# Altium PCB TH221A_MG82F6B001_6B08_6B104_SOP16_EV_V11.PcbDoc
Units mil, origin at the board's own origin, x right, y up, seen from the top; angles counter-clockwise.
Board outline 2244.09 x 2637.8 mil, 2 copper layers (Top Layer, Bottom Layer); 94 components, 67 nets, 312 pads, 160 vias.
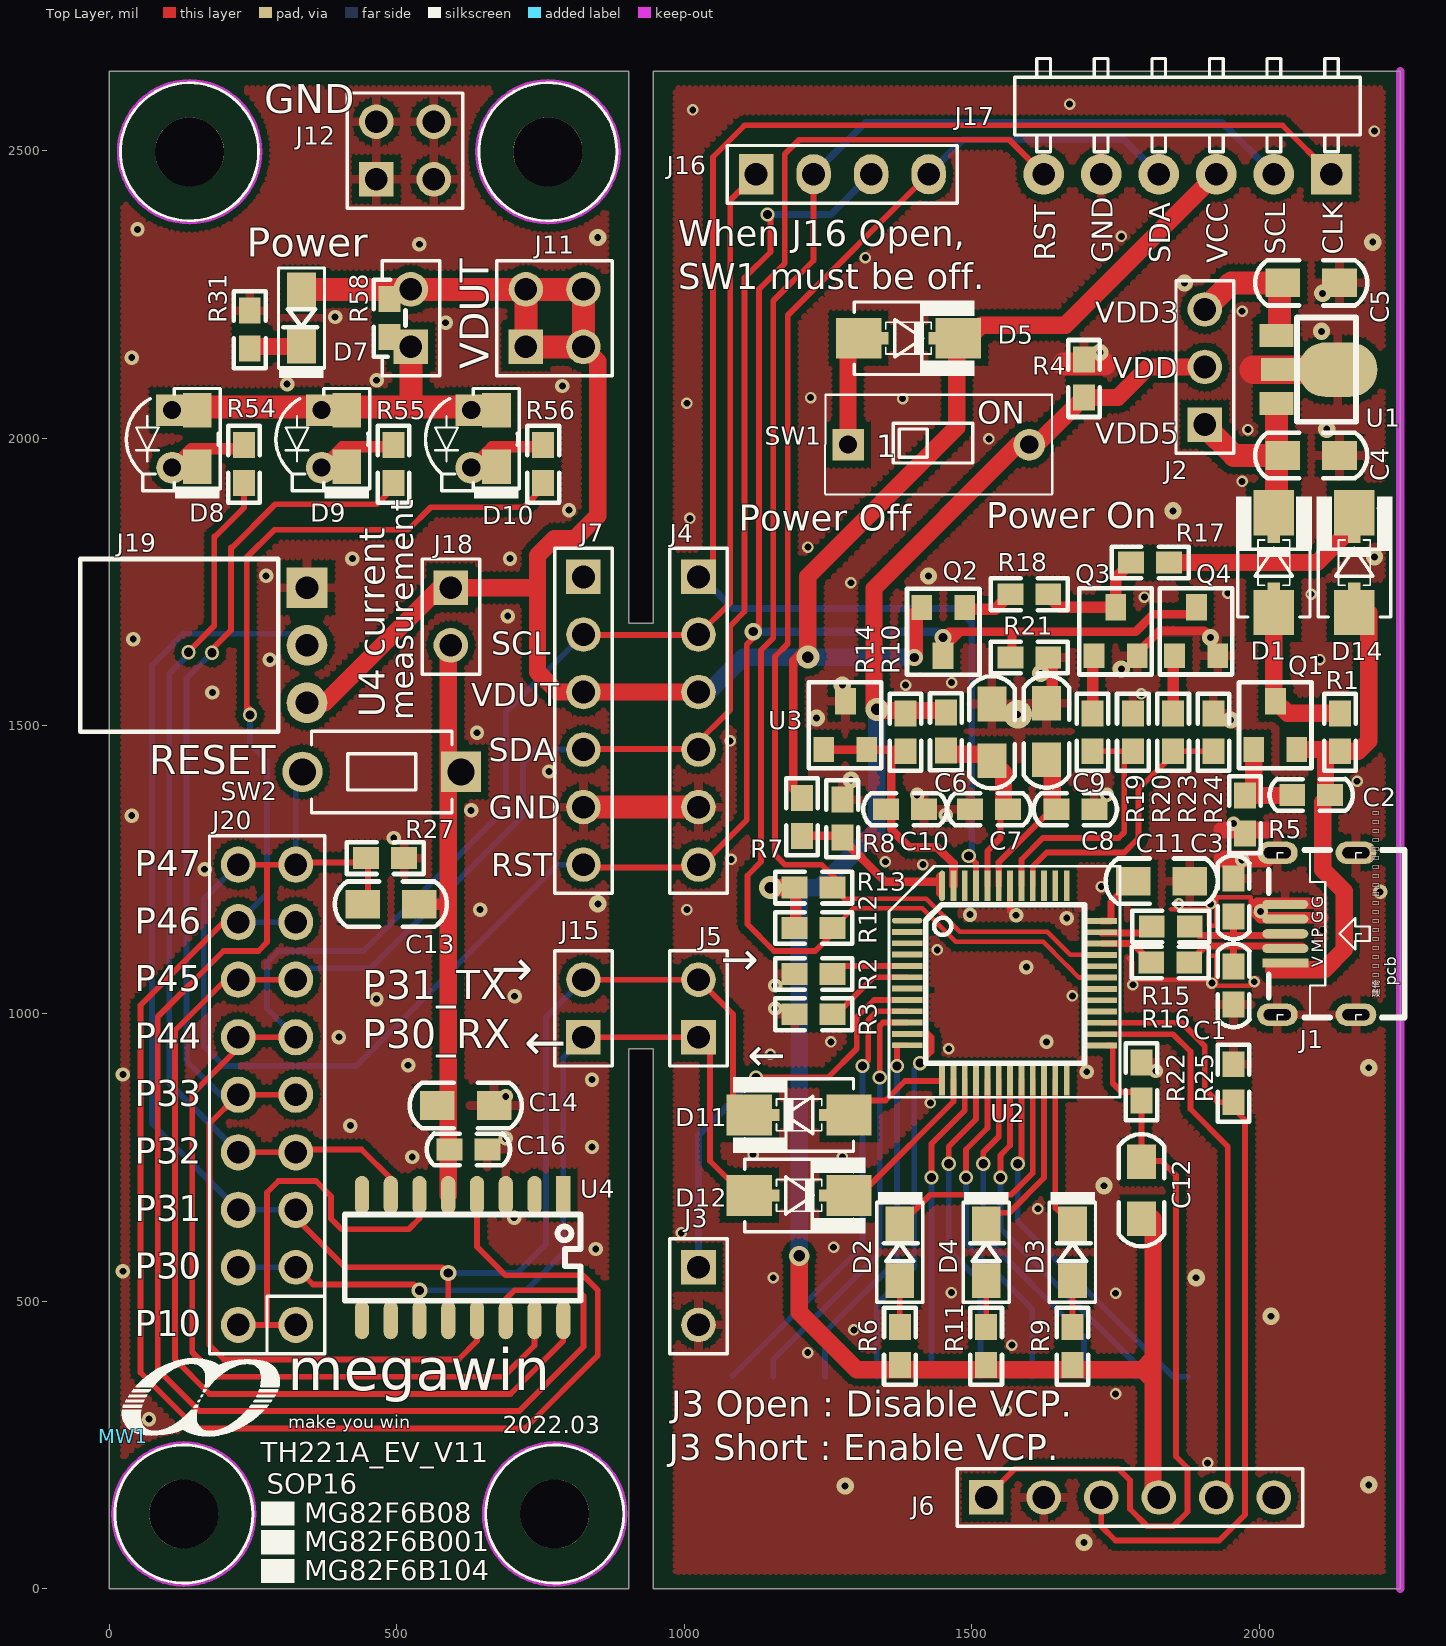
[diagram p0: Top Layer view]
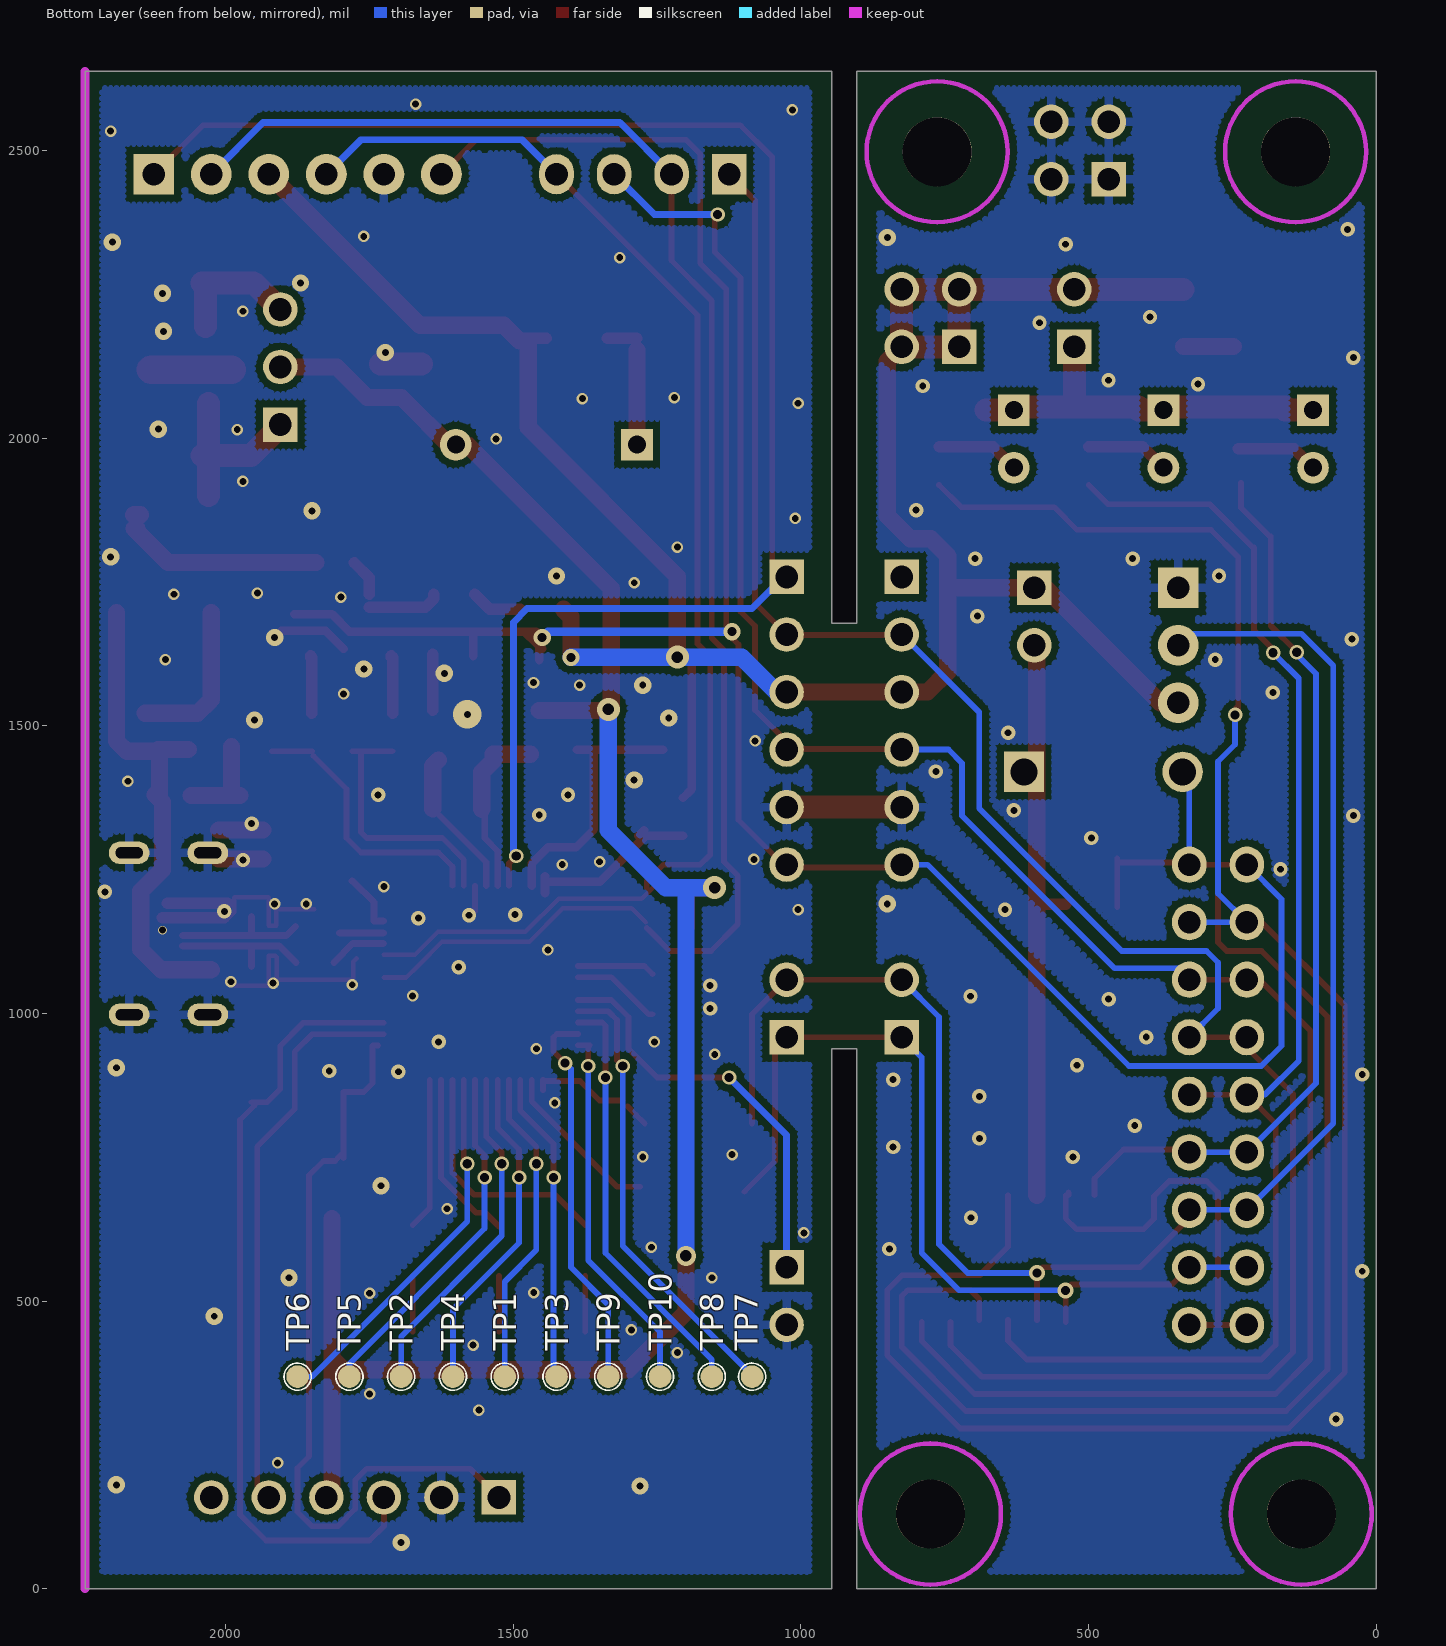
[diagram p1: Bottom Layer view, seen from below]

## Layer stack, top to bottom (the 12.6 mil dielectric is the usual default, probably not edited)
Top Layer: signal copper 1.4
Dielectric: dielectric 12.6, FR-4, Dk 4.8
Bottom Layer: signal copper 1.4

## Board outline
0,0 0,2637.8 902.99,2637.8 902.99,1678.74 946.3,1678.74 946.3,2637.8 2244.09,2637.8 2244.09,0 946.3,0 946.3,938.74 902.99,938.74 902.99,0

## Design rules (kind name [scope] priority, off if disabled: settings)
Clearance 12 [All] p1 off: gap=12
Clearance 7 [All] p2 off: gap=7
Clearance 6 [All] p3: gap=6
HoleSize 500-HoleSize [All] p1: absolutevalues=TRUE maxlimit=1500 minlimit=1 maxpercent=80.000 minpercent=20.000
PolygonConnect VIA [ISVIA] p1: connectstyle=Direct reliefconductorwidth=10 reliefentries=4 polygonreliefangle="90 Angle"
PolygonConnect "15 PolygonConnect" [All] p2: connectstyle=Relief reliefconductorwidth=15 reliefentries=4 polygonreliefangle="90 Angle"
RoomDefinition 2_MG82F6B001_6B08_6B104_V11 [InComponentClass('2_MG82F6B001_6B08_6B104_V11')] p1: confinementstyle=ConfineIn formatcopy=TRUE lockcomponents=FALSE outline -320,-225 2540,-225 2540,2735 -320,2735
RoomDefinition 1_MLink_V11 [InComponentClass('1_MLink_V11')] p2: confinementstyle=ConfineIn formatcopy=TRUE lockcomponents=FALSE outline -485,-135 2605,-135 2605,2695 -485,2695
RoutingVias [All] p1: holewidth=16 width=28 viastyle="Through Hole" minholewidth=16 minwidth=25 maxholewidth=28 maxwidth=50
ShortCircuit [All] p1 off: allowed=FALSE
SilkscreenOverComponentPads [All] p1: minsilkscreentomaskgap=10
SolderMaskExpansion [All] p1: expansion=4
UnRoutedNet [All] p1 off:
Width [All] p1: maxlimit=100 minlimit=6 preferedwidth=10
24 further rules are at their usual default settings.

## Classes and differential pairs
component class 1_MLink_V11: C1 C2 C3 C4 C5 C6 C7 C8 C9 C10 C11 C12 D1 D2 D3 D4 D5 D11 D12 D14 J1 J2 J3 J4 J5 J6 J16 J17 MW1 Q1 Q2 Q3 Q4 R1 R2 R3 R4 R5 R6 R7 R8 R9 R10 R11 R12 R13 R14 R15 R16 R17 R18 R19 R20 R21 R22 R23 R24 R25 SW1 TP1 TP2 TP3 TP4 TP5 TP6 TP7 TP8 TP9 TP10 U1 U2 U3
component class 2_MG82F6B001_6B08_6B104_V11: C13 C14 C16 D7 D8 D9 D10 J7 J11 J12 J15 J18 J19 J20 R27 R31 R54 R55 R56 R58 SW2 U4

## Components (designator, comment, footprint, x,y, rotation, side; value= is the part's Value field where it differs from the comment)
C1 "15pF" 0603C#1 1954.65,1048.74 r90 top
C2 "0.1uF" 0603C#1 2089.61,1380 r0 top
C3 "15pF" 0603C#1 1954.65,1201.74 r270 top
C4 "4.7uF" 0805C 2089.61,1970 r0 top
C5 "4.7uF" 0805C 2089.61,2270 r0 top
C6 "4.7uF" 0805C 1534.61,1488.74 r90 top
C7 "0.1uF" 0603C#1 1529.65,1355 r180 top
C8 "0.1uF" 0603C#1 1679.65,1355 r0 top
C9 "4.7uF" 0805C 1629.61,1490 r90 top
C10 "0.1uF" 0603C#1 1383.7,1355 r180 top
C11 "4.7uF" 0805C 1829.61,1230 r0 top
C12 "4.7uF" 0805C 1794.65,692.74 r90 top
C13 "4.7uF" 0805C 490,1190 r0 top
C14 "4.7uF" 0805C 620,840 r0 top
C16 "0.1uF" 0603C#2 624.65,763.74 r0 top
D1 "1N5817" DIODE_SMA_SOD323 2024.61,1783.74 r90 top
D2 "Yellow" 0805D 1374.65,585 r90 top
D3 "Green" 0805D 1674.65,585 r90 top
D4 "Red" 0805D 1524.65,585 r90 top
D5 "1N5817" DIODE_SMA_SOD323 1389.61,2173.74 r0 top
D7 "Yellow" 0805D 334.65,2208.74 r270 top
D8 "Red" LED38+0805 109.65,1998.74 r270 top
D9 "Yellow" LED38+0805 369.65,1998.74 r270 top
D10 "Green" LED38+0805 629.65,1998.74 r270 top
D11 "1N5817" DIODE_SMA_SOD323 1199.65,823.74 r180 top
D12 "1N5817" DIODE_SMA_SOD323 1199.65,683.74 r0 top
D14 "1N5817" DIODE_SMA_SOD323 2164.61,1783.74 r90 top
J1 "MICRO_USB" USB_MICRO_7.X6P065 2167.41,1138.59 r90 top
J2 "2&3 (0 ohm)" PS3P254 1904.65,2023.74 r90 top
J3 "VCP Option" PS2P254 1024.65,558.74 r270 top locked
J4 "OnBoard ICP/SWD Connector" PS6P254 1024.65,1758.74 r270 top locked
J5 "NC" PS2P254 1024.65,958.74 r90 top locked
J6 "CON6" PS6P254 1524.65,158.74 r0 top locked
J7 "CON6" PS6P254 824.65,1758.74 r270 top locked
J11 "CONN SOCKET 2x2/SM" PS2X2P254 724.65,2158.74 r0 top
J12 "CONN SOCKET 2x2/SM" PS2X2P254 464.65,2450 r0 top
J15 "NC" PS2P254 824.65,958.74 r90 top
J16 "When J16 Open, SW1 must be off." PS4P254 1124.65,2458.74 r0 top locked
J17 "Off Board ICP/SWD Connector" PS6P254_90 2124.65,2458.74 r180 top locked
J18 "JUMPER" PS2P254 594.09,1740 r270 top
J19 "3P2.54_F_90" PS3P254f_90 344.09,1740 r270 top
J20 "CON18A" PS9X2P254 324.65,458.74 r90 top
MW1 "MW-A4" MEGAWIN_3.4 24.65,265 r0 top
Q1 "IRLML6402" SOT23 2027.15,1500.71 r0 top
Q2 "2N3906" SOT23 1450.11,1663.74 r180 top
Q3 "3904" SOT23_132 1749.65,1663.74 r0 top
Q4 "3904" SOT23_132 1889.65,1663.74 r0 top
R1 "NC" 0603R#1 2139.65,1488.74 r270 top
R2 "0" 0603R#1 1224.65,1068.74 r0 top
R3 "NC" 0603R#1 1224.65,998.74 r0 top
R4 "3.3K" 0603R#1 1694.65,2103.74 r270 top
R5 "1M" 0603R#1 1974.65,1345.74 r270 top
R6 "1K" 0603R#1 1374.65,422 r270 top
R7 "30K" 0603R#1 1204.65,1341.74 r90 top
R8 "10K" 0603R#1 1274.65,1338.74 r270 top
R9 "1K" 0603R#1 1674.65,422 r270 top
R10 "10" 0603R#1 1454.61,1490 r90 top
R11 "1K" 0603R#1 1524.65,422 r270 top
R12 "1.5K" 0603R#1 1224.65,1148.74 r180 top
R13 "1.5K" 0603R#1 1224.65,1218.74 r180 top
R14 "1K" 0603R#1 1384.61,1488.74 r270 top
R15 "30" 0603R#1 1845.48,1151.05 r180 top
R16 "30" 0603R#1 1844.65,1088.74 r180 top
R17 "4.7K" 0603R#1 1809.61,1783.74 r0 top
R18 "1K" 0603R#1 1599.65,1728.74 r0 top
R19 "4.7K" 0603R#1 1709.65,1488.74 r270 top
R20 "10K" 0603R#1 1779.65,1488.74 r270 top
R21 "1M" 0603R#1 1599.65,1618.74 r180 top
R22 "47K" 0603R#1 1794.65,881.74 r90 top
R23 "4.7K" 0603R#1 1849.65,1488.74 r270 top
R24 "10K" 0603R#1 1919.65,1488.74 r270 top
R25 "47K" 0603R#1 1954.65,878.74 r270 top
R27 "47K" 0603R#2 480,1270 r0 top
R31 "1K" 0603R#1 244.65,2188.74 r90 top
R54 "470" 0603R#1 234.65,1955 r270 top
R55 "470" 0603R#1 494.65,1955 r270 top
R56 "470" 0603R#1 754.65,1955 r270 top
R58 "0" PS2p254+0603 524.65,2158.74 r90 top
SW1 "SW KEY-SPST" DIP2_SW 1284.68,1988.74 r0 top
SW2 "SW TACT-SPST" SW_T_2P 474.09,1420 r180 top
TP1 "T POINT A" PIN1_1H0 1514.65,368.74 r90 bottom
TP2 "T POINT A" PIN1_1H0 1694.65,368.74 r90 bottom
TP3 "T POINT A" PIN1_1H0 1424.65,368.74 r180 bottom
TP4 "T POINT A" PIN1_1H0 1604.65,368.74 r180 bottom
TP5 "T POINT A" PIN1_1H0 1784.65,368.74 r180 bottom
TP6 "T POINT A" PIN1_1H0 1874.65,368.74 r180 bottom
TP7 "T POINT A" PIN1_1H0 1084.65,368.74 r180 bottom
TP8 "T POINT A" PIN1_1H0 1154.65,368.74 r180 bottom
TP9 "T POINT A" PIN1_1H0 1334.65,368.74 r180 bottom
TP10 "T POINT A" PIN1_1H0 1244.65,368.74 r90 bottom
U1 "AIC1734-33(SOT-89)" SOT89 2029.61,2119.06 r270 top
U2 "MG84FG516_LQFP48" LQFP48_7X7_050 1556.12,1053.13 r270 top
U3 "TL431A" SOT23 1279.61,1500.71 r0 top
U4 "MG82F6B001/08/104 SOP-16" SO16_150P127 614.65,575.74 r270 top

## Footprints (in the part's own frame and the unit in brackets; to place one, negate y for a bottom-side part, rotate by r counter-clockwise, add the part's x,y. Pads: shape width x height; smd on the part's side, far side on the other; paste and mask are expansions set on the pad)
0603C#1 [mil]
  rect 45x38 smd: 1(33,0) 2(-33,0)
  silkscreen extent -72,-28 72,28
0603C#2 [mil]
  rect 45x38 smd: 1(-33,0) 2(33,0)
  silkscreen extent -72,-28 72,28
0603R#1 [mil]
  rect 45x38 smd: 1(33,0) 2(-33,0)
  silkscreen extent -67,-28 67,28
0603R#2 [mil]
  rect 45x38 smd: 1(-33,0) 2(33,0)
  silkscreen extent -67,-28 67,28
0805C [mil]
  rect 60x50 smd: 1(-49.21,0) 2(49.21,0)
  silkscreen extent -97,-39 97,39
0805D [mil]
  rect 60x50 smd: 1(-49.21,0) 2(49.21,0)
  silkscreen extent -87,-40 104,40
DIODE_SMA_SOD323 [mm]
  rect 2x1.8 smd: 1(-2.2,0) 2(2.2,0)
  rect 0.95x0.54 smd: 1(-1.35,0) 2(1.35,0)
  silkscreen extent -2.4,-1.68 2.92,1.68
DIP2_SW [mm]
  rect 1.4x1.4 hole 0.8: 1(0,0)
  round 1.4 hole 0.8: 2(8,0)
  silkscreen extent -1.02,-2.2 9.02,2.2
LED38+0805 [mm]
  rect 1.4x1.4 hole 0.8: 1(-1.27,0)
  rect 1.524x1.27 smd: 1(-1.267,1.11) 2(1.233,1.11)
  round 1.4 hole 0.8: 2(1.27,0)
  silkscreen extent -2.23,-2.02 2.64,2.13
LQFP48_7X7_050 [mm]
  oval 0.254x1.35 smd: 1(-2.75,-4.292)
  rect 0.254x1.35 smd: 2(-2.25,-4.292) 3(-1.75,-4.292) 4(-1.25,-4.292) 5(-0.75,-4.292) 6(-0.25,-4.292) 7(0.25,-4.292) 8(0.75,-4.292) 9(1.25,-4.292) 10(1.75,-4.292) 11(2.25,-4.292) 12(2.75,-4.292) 25(2.763,4.292) 26(2.263,4.292) 27(1.763,4.292) 28(1.263,4.292) 29(0.763,4.292) 30(0.263,4.292) 31(-0.237,4.292) 32(-0.737,4.292) 33(-1.237,4.292) 34(-1.737,4.292) 35(-2.237,4.292) 36(-2.737,4.292)
  rect 1.35x0.254 smd: 13(4.286,-2.744) 14(4.286,-2.244) 15(4.286,-1.744) 16(4.286,-1.244) 17(4.286,-0.744) 18(4.286,-0.244) 19(4.286,0.256) 20(4.286,0.756) 21(4.286,1.256) 22(4.286,1.756) 23(4.286,2.256) 24(4.286,2.756) 37(-4.286,2.756) 38(-4.286,2.256) 39(-4.286,1.756) 40(-4.286,1.256) 41(-4.286,0.756) 42(-4.286,0.256) 43(-4.286,-0.244) 44(-4.286,-0.744) 45(-4.286,-1.244) 46(-4.286,-1.744) 47(-4.286,-2.244)
  oval 1.35x0.254 smd: 48(-4.286,-2.744)
  silkscreen extent -5.15,-5.09 5.05,5.11
MEGAWIN_3.4 [mil]
  silkscreen extent -2,0 272,135
PIN1_1H0 [mm]
  round 1 smd: 1(0,0)
  silkscreen extent -0.6,-0.6 0.6,0.6
PS2P254 [mil]
  rect 60x60 hole 39.37: 1(0,0)
  round 60 hole 39.37: 2(100,0)
  silkscreen extent -50,-50 150,50
PS2p254+0603 [mil]
  rect 60x60 hole 39.37: 1(0,0)
  rect 45x38 smd: 1(17,36.85) 2(83,36.85)
  round 60 hole 39.37: 2(100,0)
  silkscreen extent -50,-50 150,64
PS2X2P254 [mil]
  rect 60x60 hole 39.37: 1(0,0)
  round 60 hole 39.37: 2(0,100) 3(100,0) 4(100,100)
  silkscreen extent -50,-50 150,150
PS3P254 [mil]
  rect 60x60 hole 39.37: 1(0,0)
  round 60 hole 39.37: 2(100,0) 3(200,0)
  silkscreen extent -50,-50 250,50
PS3P254f_90 [mm]
  rect 1.8x1.8 hole 1: 1(0,0)
  round 1.8 hole 1: 2(2.54,0) 3(5.08,0)
  silkscreen extent -1.27,-10 6.35,-1.27
PS4P254 [mil]
  rect 60x70 hole 39.37: 1(0,0)
  oval 60x70 hole 39.37: 2(100,0) 3(200,0) 4(300,0)
  silkscreen extent -50,-50 350,50
PS6P254 [mil]
  rect 60x60 hole 39.37: 1(0,0)
  round 60 hole 39.37: 2(100,0) 3(200,0) 4(300,0) 5(400,0) 6(500,0)
  silkscreen extent -50,-50 550,50
PS6P254_90 [mm]
  rect 1.8x1.8 hole 1: 1(0,0)
  round 1.8 hole 1: 2(2.54,0) 3(5.08,0) 4(7.62,0) 5(10.16,0) 6(12.7,0)
  silkscreen extent -1.27,-5.11 13.97,-1
PS9X2P254 [mm]
  oval 1.6x1.524 hole 1: 1(0,0) 2(0,2.54) 4(2.54,2.54) 5(5.08,0) 6(5.08,2.54) 7(7.62,0) 8(7.62,2.54) 9(10.16,0) 10(10.16,2.54) 11(12.7,0) 12(12.7,2.54) 13(15.24,0) 14(15.24,2.54) 15(17.78,0) 16(17.78,2.54) 17(20.32,0) 18(20.32,2.54)
  round 1.524 hole 1: 3(2.54,0)
  silkscreen extent -1.27,-1.27 21.59,3.81
SO16_150P127 [mil]
  rect 67x25 smd: 1(-108.5,175)
  oval 67x25 smd: 2(-108.5,125) 3(-108.5,75) 4(-108.5,25) 5(-108.5,-25) 6(-108.5,-75) 7(-108.5,-125) 8(-108.5,-175) 9(108.5,-175) 10(108.5,-125) 11(108.5,-75) 12(108.5,-25) 13(108.5,25) 14(108.5,75) 15(108.5,125) 16(108.5,175)
  silkscreen extent -75,-205 75,205
SOT23 [mil]
  rect 36x43.31 smd: 1(-37.5,-41.97) 2(37.5,-41.97)
  rect 36x46.06 smd: 3(0.5,41.97)
  silkscreen extent -63,-74 63,75
SOT23_132 [mil]
  rect 36x43.31 smd: 1(-37.5,-41.97) 3(37.5,-41.97)
  rect 36x46.06 smd: 2(0.5,41.97)
  silkscreen extent -63,-74 63,75
SOT89 [mm]
  rect 1.016x1.5 smd: 1(-1.5,0) 3(1.5,0)
  oval 2.4x3.5 smd: 2(0,2.7)
  rect 1.016x2.6 smd: 2(0,0.6)
  silkscreen extent -2.3,0.9 2.3,3.5
SW_T_2P [mil]
  rect 70x70 hole 47.24: 1(-137.79,0)
  round 70 hole 47.24: 2(137.79,0)
  silkscreen extent -122,-71 122,71
USB_MICRO_7.X6P065 [mm] "J?"
  rect 0.4x2.032 smd: 1(-1.3,3.119)
  oval 0.4x2.032 smd: 2(-0.65,3.119) 3(0,3.119) 4(0.65,3.119) 5(1.3,3.119)
  oval 1x1.8 hole 0.5 slot 1.2 at 90 deg: 6(3.575,3.47) 7(3.575,0) 8(-3.575,0) 9(-3.575,3.47)
  silkscreen extent -3.83,-2.15 3.7,3.85

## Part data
C1 C3 C7 C12 C13 C14 C16: library part "CAP NP_Dup1"
C2 C8 C10: library part "CAP NP"
C4 C5: library part "C NP"
C6 C9 C11: library part CAP
D1 D5 D11 D12 D14: library part "DIODE SCHOTTKY"
D2 D3 D4: library part Led0_0
D7 D8 D9 D10: library part LED
J1: library part USB_Micro
J2 J19: library part CON3
J3 J5 J15: library part CON2
J4 J17: library part CON6
J7: library part CON6_Dup1
J16: library part CON4
MW1: library part MW_A4_2
Q1: library part "MOSFET P GSD"
Q2: library part 2N3906_0
Q3 Q4: library part "NPN BCE"
R1 R2 R3 R4: library part R_Dup4
R5 R6 R7 R8 R9 R11 R12 R13 R17 R18 R19 R22 R23 R25 R27: library part R_Dup2
R10 R14 R15 R16: library part R_Dup5
R20 R21 R24: library part R_Dup1
R31 R54 R55 R56 R58: library part R_Dup3
U1: library part AIC1722-33
U3: library part TL431/CYL
U4: library part MG82F6B001/08/104_SOP-16

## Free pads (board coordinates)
  round 120 hole 120 unplated: 0(130,130) 0(140,2497.8) 0(762.99,2497.8) 0(774.65,130)

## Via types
v1: diameter 20, hole 12, Top Layer to Bottom Layer, tented both sides, 54 vias
v2: diameter 25, hole 12, Top Layer to Bottom Layer, tented both sides, 54 vias
v3: diameter 30, hole 12, Top Layer to Bottom Layer, tented both sides, 25 vias
v4: diameter 25, hole 16, Top Layer to Bottom Layer, tented both sides, 16 vias
v5: diameter 40, hole 20, Top Layer to Bottom Layer, tented both sides, 3 vias
v6: diameter 30, hole 16, Top Layer to Bottom Layer, tented both sides, 3 vias
v7: diameter 28, hole 16, Top Layer to Bottom Layer, tented both sides, 2 vias
v8: diameter 15, hole 12, Top Layer to Bottom Layer, tented both sides, 1 vias
v9: diameter 50, hole 12, Top Layer to Bottom Layer, tented both sides, 1 vias
v10: diameter 35, hole 20, Top Layer to Bottom Layer, tented both sides, 1 vias

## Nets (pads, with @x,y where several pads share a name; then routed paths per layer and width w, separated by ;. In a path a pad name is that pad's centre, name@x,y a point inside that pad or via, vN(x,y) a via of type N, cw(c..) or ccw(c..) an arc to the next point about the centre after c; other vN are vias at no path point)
2.495V: C10.1 R14.1 U2.47 U3.1 U3.2 | length 455.3
  Top Layer w15: U3.1@1239.61,1458.74 U3.1 U3.2 1359.61,1458.74 1359.61,1455.74 1359.61,1355 1359.61,1320 1390.87,1288.74 1439.65,1288.74 1467.78,1260.6 U2.47 ; 1364.61,1458.74 1384.61,1458.74 R14.1@1389.61,1458.74
516P24: TP7.1 U2.9 | length 790.4
  Top Layer w10: v4(1309.65,908.74) 1319.65,918.74 1319.65,988.74 1334.82,1003.92 U2.9
  Bottom Layer w10: TP7.1@1083.51,369.88 1309.65,596.02 v4(1309.65,908.74)
516P25: TP8.1 U2.10 | length 736.4
  Top Layer w10: v4(1339.65,888.74) 1339.65,978.74 1345.14,984.23 U2.10
  Bottom Layer w10: TP8.1 1154.65,398.59 1339.65,583.59 v4(1339.65,888.74)
516P26: TP9.1 U2.11 | length 674.3
  Top Layer w10: U2.11 1423.84,964.55 1429.65,958.74 1429.65,933.74 v4(1409.65,913.74)
  Bottom Layer w10: TP9.1 1334.65,493.74 1399.65,558.74 1399.65,903.74 v4(1409.65,913.74)
516P27: TP10.1 U2.12 | length 649.5
  Top Layer w10: v4(1369.65,908.74) 1369.65,941.97 1366.75,944.86 U2.12
  Bottom Layer w10: TP10.1 1244.65,446.17 1369.65,571.17 v4(1369.65,908.74)
516P32: TP3.1 U2.15 | length 762.5
  Top Layer w10: v4@1429.65,713.74 v4(1429.65,715) 1429.65,773.74 1487.47,831.56 U2.15
  Bottom Layer w10: TP3.1@1429.65,373.74 1429.65,628.74 ; 1429.65,400.87 1429.65,628.74 ; v4@1429.65,713.74 1429.65,628.74
516P33: TP1.1 U2.16 | length 558.1
  Top Layer w10: v4(1459.65,738.74) 1459.65,768.74 1507.15,816.25 U2.16
  Bottom Layer w10: v4(1459.65,738.74) 1459.65,588.89 1514.65,533.89 TP1.1
516P34: TP4.1 U2.17 | length 578.7
  Top Layer w10: v4@1489.65,713.74 v4(1489.65,715) 1489.65,763.74 1526.84,800.93 U2.17
  Bottom Layer w10: v4@1489.65,713.74 1489.65,601.31 1604.65,486.31 TP4.1
516P35: TP2.1 U2.18 | length 599.3
  Top Layer w10: v4(1519.65,738.74) 1519.65,758.74 1546.52,785.62 U2.18
  Bottom Layer w10: v4(1519.65,738.74) 1519.65,613.74 1694.65,438.74 TP2.1
516P36: TP5.1 U2.19 | length 619.9
  Top Layer w10: v4@1549.65,713.74 v4(1549.65,715) 1549.65,753.74 1566.21,770.3 U2.19
  Bottom Layer w10: v4@1549.65,713.74 1549.65,626.17 1784.65,391.17 TP5.1
516P37: TP6.1 U2.20 | length 655.2
  Top Layer w10: v4(1579.65,738.74) 1585.89,744.99 U2.20
  Bottom Layer w10: v4(1579.65,738.74) 1579.65,638.59 1849.5,368.74 TP6.1
CHIP_VDD: C13.2 C14.1 C16.1 J18.2 SW2.1 U4.5 | length 1016.2
  Top Layer w20: C13.2 589.65,1190
  Top Layer w30: U4.5 589.65,763.74 589.65,840 589.65,1190 589.65,1420 589.65,1640 J18.2@589.65,1650
D+: C3.1 J1.3 R15.2 | length 231.2
  Top Layer w12: R15.2 1894.32,1135.21 2044.61,1135.21 J1.3@2074.65,1135.21 ; 1954.65,1140.21 C3.1
D-: C1.1 J1.2 R16.2 | length 239.3
  Top Layer w12: R16.2 1906.12,1117.21 2044.61,1117.21 J1.2@2074.65,1117.21 ; C1.1 1954.65,1112.21
DET_VDUT: R7.2 R8.1 U2.48 | length 318.6
  Top Layer w15: R7.2 1274.65,1308.74 R8.1@1282.2,1308.74 ; R8.1@1272.2,1318.74 R8.1@1279.93,1311.02 ; R8.1@1272.41,1305.98 1273.65,1304.74 1349.65,1228.74 1440.58,1228.74 ; U2.48@1444.65,1208.74 1444.65,1221.87 U2.48@1444.65,1238.74
DUT_CLK: J4.1 J17.1 U2.45 | length 2846.4
  Top Layer w10: J4.1 1049.65,1783.74 1049.65,2488.74 1104.65,2543.74 2039.65,2543.74 J17.1 ; v4(1494.53,1273.74) 1507.15,1261.11 U2.45
  Bottom Layer w12: J4.1 1029.65,1758.74 1084.65,1703.74 1475.87,1703.74 1499.61,1680 1499.61,1278.82 v4(1494.53,1273.74)
DUT_RST: C13.1 J4.6 J7.6 J17.6 J20.17 J20.18 Q2.3 Q4.2 R21.1 R27.1 SW2.2 U4.14 | length 6694.6
  Top Layer w10: J20.18 274.65,1258.74 ; J20.17@321.65,1261.74 318.65,1258.74 274.65,1258.74 ; J20.17@327.09,1262.44 R27.1@447,1262.44 ; C13.1@450,1185 450,1190 R27.1@450,1270 ; U4.14 689.65,503.74 704.65,518.74 814.65,518.74 824.65,508.74 ; 824.65,443.74 824.65,508.74 ; J7.6@824.65,1253.74 J4.6@1024.65,1253.74 ; J4.6@1027.65,1255.74 1108.4,1336.49 1108.4,1641.49 1125.15,1658.24 1129.65,1662.74 1129.65,1663.74 1129.65,2258.74 1174.65,2303.74 1174.65,2493.74 1199.65,2518.74 1564.65,2518.74 J17.6 ; 274.65,1258.74 274.65,1123.74 259.65,1108.74 199.09,1108.74 84.65,994.29 84.65,381.17 156.78,309.03 713.13,309.03 824.65,420.55 824.65,508.74
  Top Layer w15: Q2.3@1449.61,1633.74 Q2.3@1454.61,1638.74 ; v6(1449.61,1653.74) 1459.61,1663.74 1479.61,1663.74 ; Q2.3@1454.61,1613.74 1454.61,1621.77 Q2.3@1454.61,1638.74 ; v6@1454.61,1656.74 1454.61,1653.74 Q2.3@1454.61,1638.74 ; R21.1@1569.61,1620.74 1569.61,1663.74 ; Q4.2@1880.23,1693.74 1814.61,1693.74 1784.61,1663.74 1569.61,1663.74 ; Q2.3@1454.61,1638.74 1459.61,1643.74 1479.61,1663.74 ; 1479.61,1663.74 1569.61,1663.74
  Bottom Layer w10: J20.18 164.65,1198.74 164.65,943.74 199.65,908.74 429.65,908.74 779.65,1258.74 J7.6 ; J20.17 324.65,1420 SW2.2@324.65,1440
  Bottom Layer w12: J7.6@814.65,1248.74 J7.6@824.65,1238.74
  Bottom Layer w15: v6(1119.65,1663.74) 1439.61,1663.74 v6(1449.61,1653.74)
FAIL: D4.2 U2.22 | length 305.7
  Top Layer w10: D4.2@1524.65,629.74 1526.88,631.98 1548.65,653.74 1564.65,653.74 1625.26,714.36 U2.22
GND_POWER: C1.2 C3.2 C4.2 C5.2 C6.2 C7.1 C8.1 C9.2 C10.2 C11.2 C14.2 C16.2 J1.4 J1.5 J1.6 J1.7 J1.8 J1.9 J3.2 J4.5 J6.2 J7.5 J12.1 J12.2 J12.3 J12.4 J17.5 J19.1 Q3.3 Q4.3 R2.2 R3.2 R4.2 R5.1 R8.2 R20.2 R21.2 R22.1 R24.2 R25.2 R27.2 R31.1 U1.2 U2.42 U3.3 U4.3 | length 1656.7
  Top Layer w8: 1772.15,1095.71 1778.15,1089.71 1778.15,1058.74 1779.61,1058.74 1844.15,1058.74 ; 1845.15,1058.74 1911.15,1058.74 1911.15,1098.2 ; 1845.98,1181.05 1859.61,1181.05 1911.98,1181.05 1911.98,1152.21 1924.65,1152.21 1924.65,1190.64 1924.65,1202.24 1984.65,1202.24 1984.65,1176.01 1992.44,1168.22 1994.61,1166.05 ; 1913.16,1100.21 1924.65,1100.21 1924.65,1052.74 1924.65,1048.24 1984.65,1048.24 v1@1984.65,1055.24
  Top Layer w10: 1566.21,1177.75 U2.42
  Top Layer w15: Q3.3@1794.89,1634.03 1825.85,1664.98 1903.31,1664.98 v3(1914.55,1653.74)
  Top Layer w20: C9.2@1639.65,1526.74 1639.65,1539.21 1639.65,1591.18 1639.65,1618.74 R21.2@1639.65,1624.27 ; 1995.68,1191.64 2001.82,1191.64 2044.61,1191.64 2101.59,1191.64 ; v2@2001.82,1166.05 2044.61,1166.05 2109.55,1166.05
  Top Layer w30: 1934.65,1268.74 1954.65,1268.74 1969.55,1268.74 J1.6@2011.65,1268.74 ; 1934.65,1318.74 1954.61,1318.74 1974.65,1318.74 2011.65,1318.74
  Top Layer w40: J7.5 J4.5 ; 1659.55,2128.74 1694.65,2128.74 1722.2,2128.74 1730.65,2128.74
  Top Layer w50: 1989.61,2119.06 2053.23,2119.06 U1.2@2129.61,2119.06
  other v1: 1909.55,218.74 1559.61,310.64 1749.55,338.74 1214.61,410.64 1569.55,423.74 1294.61,450 1749.55,513.74 1464.09,515 1154.61,540.64 1259.55,593.74 994.65,618.74 1614.65,660.64 1274.65,750.64 1119.55,754.74 1427.65,844.74 1149.55,928.74 1459.55,938.74 1254.61,950.64 1674.65,1030.64 1779.61,1050 1917.15,1052.74 1990.65,1055.24 1439.65,1110.64 1004.65,1180.64 1859.61,1190.58 1914.61,1190.64 1724.65,1220.64 1414.65,1258.74 1349.55,1263.74 1081.61,1268 2169.55,1403.74 1079.55,1473.74 1794.61,1555.67 1384.61,1570.64 1464.61,1575 2104.61,1615 1799.55,1723.74 2089.55,1728.74 1944.61,1730.64 1289.55,1748.74 1214.65,1810.64 1009.61,1860.64 1969.61,1925 1529.55,1998.74 1979.55,2015 1004.61,2060.64 1379.55,2068.74 1219.65,2070.64 1969.61,2220.64 1314.65,2313.74 1759.65,2350.64 2199.55,2533.74 1014.61,2570.64 1669.61,2580.64
  other v2: 69.55,295 24.09,552 846.09,590.64 704.09,645 527.09,750.64 839.55,768 689.55,783 419.55,805 689.55,856 839.55,885 24.09,894 1699.55,898.74 1819.61,900 520,910 1629.61,950.64 399.55,959 1157.72,1008.74 465,1025 705,1030 1157.72,1048.74 1594.65,1080.64 1664.65,1165.74 1576.65,1170.74 1496.65,1171.74 2001.82,1177.6 645.09,1180.64 2209.55,1211.45 166.09,1250.64 1969.55,1266.74 495,1305 1954.61,1330 39.55,1344 1454.61,1345 629.55,1353 1404.61,1380 1734.61,1380 765.09,1420.64 639.55,1488 179.55,1558 279.55,1615 42.09,1650.64 693.09,1690.64 273.09,1760.64 423.09,1790.64 697.09,1790.64 799.55,1875 788.09,2090.64 309.55,2094 465.09,2100.64 39.55,2140 585.09,2200.64 393.09,2210.64 539.55,2337 49.55,2363
  other v3: 1694.65,80.64 1279.55,178.74 2189.65,180.64 2019.55,473.74 1889.61,540.64 1729.65,700.64 2189.65,905.64 849.65,1190.64 1289.61,1405.67 1949.61,1510 1229.55,1513.74 1274.65,1570.64 1619.61,1591.18 1759.55,1598.74 1424.61,1760.64 2199.55,1793.74 1849.61,1873.74 2116.65,2015.64 1722.2,2148.74 2107.65,2185.64 2109.55,2251.74 1869.55,2269.74 2196.65,2340.64 849.55,2348.74
  other v8: 2109.55,1145
  other v9: 1579.61,1520
ICP/SWD_SCL: J16.2 J17.2 R12.2 U2.31 | length 2959.9
  Top Layer w8: R12.2@1269.65,1158.74 1293.65,1182.74 1413.6,1182.74 1471.6,1124.74 1623.6,1124.74 1663.5,1084.84 ; 1663.54,1084.84 1685.91,1062.47 U2.31
  Top Layer w10: J16.2@1224.65,2483.74 J16.2 1224.65,2308.74 1154.65,2238.74 1154.65,1652.74 1133.4,1631.49 1133.4,1263.79 1109.61,1240 1109.61,1155 1155.87,1108.74 1227.65,1108.74 1262.65,1143.74 R12.2@1267.65,1148.74
  Bottom Layer w12: J16.2 1314.65,2548.74 1934.65,2548.74 J17.2
ICP/SWD_SDA: J16.4 J17.4 R13.2 U2.33 | length 2399.4
  Top Layer w8: R13.2 1276.65,1199.74 1420.65,1199.74 1478.65,1141.74 1630.65,1141.74 1670.54,1101.84 U2.33
  Top Layer w10: R13.2@1267.65,1218.74 1267.65,1229.74 1238.65,1258.74 1174.65,1258.74 1157.4,1275.99 1157.4,1620.49 1179.65,1642.74 1179.65,2213.74 J16.4
  Bottom Layer w12: J16.4 1484.65,2518.74 1764.65,2518.74 J17.4
MLINK_RXD: D11.2 J5.2 J15.2 J19.2 J20.5 J20.6 U4.12 | length 2958.5
  Top Layer w10: J20.5 324.65,644.45 410.35,558.74 579.65,558.74 v7(589.65,548.74) U4.12@589.65,473.74 ; U4.12 U4.12@589.65,473.74 ; 589.65,503.74 U4.12@589.65,473.74 ; J15.2 J5.2 1084.65,998.74 1084.65,823.74 D11.2@1084.65,808.74
  Bottom Layer w10: J20.6 74.65,808.74 74.65,1605 129.65,1660 J19.2@344.09,1660 ; J20.6@249.65,658.74 J20.5 ; v7(589.65,548.74) 709.65,548.74 759.65,598.74 759.65,993.74 J15.2
MLINK_TXD: D12.1 J5.1 J15.1 J20.3 J20.4 U4.11 | length 1570.9
  Top Layer w10: J20.3@329.65,563.74 J20.3 ; J20.3@334.65,548.74 J20.3 ; U4.11@539.65,463.74 U4.11 v7(539.65,518.74) 529.65,528.74 354.65,528.74 J20.3 ; J15.1 J5.1 J5.1@1030.41,952.97 ; J5.1@1044.65,956.74 1044.65,743.74 D12.1@1098.03,690.35
  Bottom Layer w10: J20.4 J20.3 ; v7(539.65,518.74) 724.65,518.74 789.65,583.74 789.65,923.74 J15.1
NetC2_2: C2.2 Q1.1 R5.2 | length 170
  Top Layer w30: R5.2 R5.2@1989.65,1378.74 ; Q1.1@1989.65,1463.74 Q1.1 R5.2@1989.65,1378.74 ; C2.2@2059.65,1378.74 2056.61,1378.74 R5.2@1989.65,1378.74
NetC6_1: C6.1 C7.2 R10.2 U2.44 | length 306.5
  Top Layer w11: U2.44 1526.84,1282.23 1549.61,1305 C7.2@1549.61,1350
  Top Layer w30: R10.2@1469.65,1450.74 1534.61,1450.74 C6.1 1554.61,1419.53 C7.2@1554.61,1355
NetC8_2: C8.2 C9.1 U2.43 | length 261.6
  Top Layer w11: U2.43 1546.52,1262.92 C8.2@1639.61,1356
  Top Layer w30: C9.1 1639.61,1430.79 C8.2@1639.61,1356
NetC11_1: C11.1 U2.36 | length 103.2
  Top Layer w12: U2.36 1741.8,1160.9 1741.8,1193.42 1779.02,1230.64 C11.1@1780.39,1230.64
NetD1_1: D1.1 Q1.3 R1.2 | length 306
  Top Layer w30: D1.1@2024.61,1697.13 2024.61,1545.72 Q1.3 ; R1.2 2048.58,1521.74 ; Q1.3 2048.58,1521.74 ; Q1.3 2048.58,1521.74
NetD2_1: D2.1 R6.2 | length 97
  Top Layer w10: R6.2@1374.65,446.74 R6.2 D2.1 D2.1@1374.65,543.74
NetD3_1: D3.1 R9.2 | length 97
  Top Layer w10: R9.2@1674.65,446.74 R9.2 D3.1 D3.1@1674.65,543.74
NetD4_1: D4.1 R11.2 | length 97
  Top Layer w10: R11.2@1524.65,446.74 R11.2 D4.1 D4.1@1524.65,543.74
NetD5_1: D5.1 SW1.1 | length 215.1
  Top Layer w20: D5.1@1285.47,2173.74 1302.99,2173.74 D5.1@1336.46,2173.74
  Top Layer w30: SW1.1 D5.1@1284.68,2152.87
NetD7_2: D7.2 R31.2 | length 86.2
  Top Layer w30: R31.2@248.43,2159.53 D7.2
NetD8_1: D8.1 D9.1 D10.1 R58.1 | length 716.6
  Top Layer w40: D8.1@109.65,2048.74 153.33,2048.74 D8.1@158.33,2048.74 ; D8.1@158.33,2054.61 D9.1@369.65,2054.61 ; D9.1@369.65,2048.61 D9.1@413.33,2048.61 ; D9.1@369.65,2048.74 D9.1@413.33,2048.74 ; D9.1@413.33,2054.61 524.65,2054.61 ; R58.1@524.65,2158.74 524.65,2054.61 ; D10.1@629.65,2048.61 673.33,2048.61 678.07,2048.61 678.2,2048.74 D10.1@678.33,2048.61 ; D10.1@629.65,2054.61 524.65,2054.61
NetD8_2: D8.2 R54.2 | length 143.7
  Top Layer w20: D8.2@109.65,1948.74 132.21,1971.3 142.65,1981.74 153.33,1981.74 234.65,1981.74 R54.2@239.65,1981.74
NetD9_2: D9.2 R55.2 | length 144.9
  Top Layer w20: D9.2@369.65,1948.74 392.21,1971.3 405.65,1984.74 413.33,1984.74 494.65,1984.74 R55.2@499.65,1984.74
NetD10_2: D10.2 R56.2 | length 144.9
  Top Layer w20: D10.2@629.65,1948.74 652.21,1971.3 665.65,1984.74 673.33,1984.74 754.65,1984.74 R56.2@759.65,1984.74
NetD11_1: D11.1 U2.13 | length 209.6
  Top Layer w10: D11.1@1271.26,808.74 1286.26,823.74 D11.1@1301.26,838.74 ; D11.1@1309.65,848.74 1349.65,848.74 1383.71,882.8 U2.13@1445.56,882.8 ; U2.13@1448.1,867.19 U2.13
NetD12_2: D12.2 U2.14 | length 287
  Top Layer w10: D12.2@1279.65,698.74 1286.26,698.74 1319.65,698.74 1467.78,846.88 U2.14
NetD14_2: D14.2 R17.1 | length 348.7
  Top Layer w30: R17.1 2094.61,1783.74 ; 2099.61,1783.74 D14.2@2158.68,1842.81 ; D14.2@2147.76,1866.89 D14.2@2159.61,1866.89 ; D14.2@2153.68,1842.81 D14.2@2154.61,1843.74
NetQ2_1: Q2.1 R18.2 | length 89.8
  Top Layer w20: Q2.1@1487.61,1702.68 1540.58,1702.68 R18.2
NetQ3_1: Q3.1 R19.2 | length 117.1
  Top Layer w20: R19.2@1709.65,1538.78 R19.2 Q3.1@1709.65,1619.27 ; Q3.1@1712.15,1619.27 Q3.1
NetQ3_2: Q3.2 R17.2 R18.1 | length 192.7
  Top Layer w20: R18.1@1637.65,1728.74 1637.65,1720.7 1652.64,1705.71 Q3.2 ; 1750.15,1728.74 1750.15,1757.28 R17.2
NetQ4_1: Q4.1 R23.2 | length 100
  Top Layer w20: R23.2 Q4.1@1849.65,1619.27 ; Q4.1@1852.15,1619.27 Q4.1
NetR15_1: R15.1 U2.35 | length 108.8
  Top Layer w12: U2.35@1725.11,1140.21 1754.65,1140.21 ; 1786.91,1140.21 1754.65,1140.21 ; R15.1@1801.65,1140.21 1754.65,1140.21
NetR16_1: R16.1 U2.34 | length 100.1
  Top Layer w12: U2.34 1778.86,1121.53 R16.1
OCD_CLK/P44: J4.2 J7.2 J16.1 J20.11 J20.12 U4.15 | length 3474
  Top Layer w10: J20.11 J20.12 224.65,940 144.65,860 144.65,411.31 187.22,368.74 685.41,368.74 739.65,422.98 U4.15@739.65,446.17 ; 739.65,426.17 U4.15@739.65,446.17 ; U4.15@739.65,463.74 U4.15@739.65,446.17 ; J7.2@824.65,1657.74 J4.2@1024.65,1657.74 ; J4.2 1079.65,1713.74 1079.65,2413.74 J16.1
  Bottom Layer w10: J20.11 274.65,1008.74 274.65,1088.74 294.65,1108.74 442.22,1108.74 689.65,1356.17 689.65,1523.74 J7.2
  Bottom Layer w12: J7.2@809.65,1673.74 J7.2
OCD_SDA/P45: J4.4 J7.4 J16.3 J20.13 J20.14 U4.16 | length 3681.1
  Top Layer w10: J20.14@204.09,1060 114.65,970.55 114.65,398.89 174.79,338.74 697.83,338.74 789.65,430.55 U4.16@789.65,453.74 ; J20.14 J20.13 ; 789.65,433.74 U4.16@789.65,453.74 ; U4.16@789.65,463.74 U4.16@789.65,453.74 ; J7.4@824.65,1459.74 J4.4@1010.65,1459.74 ; J4.4@1017.65,1465.74 1079.65,1527.74 1079.65,1673.74 1104.65,1698.74 1104.65,2278.74 1149.65,2323.74 v4@1149.65,2388.74
  Bottom Layer w10: J20.13 344.65,1078.74 454.65,1078.74 719.65,1343.74 719.65,1435 743.39,1458.74 J7.4
  Bottom Layer w12: v4(1144.65,2388.74) 1254.65,2388.74 J16.3
P10: J20.1 J20.2 U4.6 | length 799.5
  Top Layer w10: J20.2 274.65,458.74 ; J20.1 274.65,458.74 ; 423.39,625 509.09,625 ; U4.6@534.65,684.24 U4.6@534.65,688.74 ; U4.6 539.65,643.74 520.91,625 509.09,625 ; 274.65,458.74 274.65,688.74 294.65,708.74 359.65,708.74 385.91,682.48 385.91,643.18 404.09,625 509.09,625
P32: J20.7 J20.8 R54.1 U4.7 | length 1675.8
  Top Layer w10: v4@137.59,1628.5 183.09,1674 183.09,1827.54 ; 183.09,1829.54 183.09,1827.54 ; J20.8 J20.7 329.65,763.74 439.09,763.74 489.65,713.19 U4.7 ; R54.1 234.65,1879.1 183.09,1827.54
  Bottom Layer w10: v4@134.09,1620 104.65,1590.55 104.65,878.74 J20.8 J20.7
  other v4: 138.09,1628
P33: J20.9 J20.10 R55.1 U4.13 | length 2451.2
  Top Layer w10: v4@176.09,1630 212.09,1665.99 212.09,1807.99 ; 212.09,1809.99 212.09,1807.99 ; J20.9 J20.10 174.65,808.74 174.65,423.74 199.65,398.74 607.37,398.74 639.65,431.02 U4.13 ; R55.1@499.65,1918.74 498.78,1917.87 465.91,1885 289.09,1885 212.09,1807.99
  Bottom Layer w10: v4(179.09,1627) 134.65,1582.55 134.65,917.63 193.53,858.74 J20.10
P44: J6.5 U2.26 | length 977.3
  Top Layer w10: U2.26 1849.34,964.05 1879.65,933.74 1879.65,833.74 1944.65,768.74 1944.65,178.74 J6.5
P45: J6.3 R25.1 U2.27 | length 1381.3
  Top Layer w10: J6.3 1724.65,108.74 1749.65,83.74 1929.65,83.74 1974.65,128.74 1974.65,814.96 R25.1@1949.61,840 ; U2.27 1864.65,983.73 1904.65,943.74 1904.65,868.74 1927.65,845.74 R25.1
P46: J20.15 J20.16 R56.1 U4.4 | length 3648.7
  Top Layer w10: J20.16 199.09,1158.74 54.65,1014.29 54.65,376.17 152.07,278.74 722.83,278.74 849.65,405.55 849.65,519.45 ; v4@239.55,1519 239.55,1534 ; v4@249.82,1523.73 239.55,1534 ; U4.4@639.65,680.74 U4.4 639.65,594.45 689.09,545 824.09,545 849.65,519.45 ; R56.1@759.65,1918.74 758.78,1917.87 720.91,1880 559.09,1880 519.74,1840.64 287.19,1840.64 239.55,1793 239.55,1534 ; 849.65,428.74 849.65,519.45
  Bottom Layer w10: v4(245.09,1519) 245.09,1467.55 274.65,1438 274.65,1208.74 J20.16 J20.15
PASS: D3.2 U2.23 | length 264.5
  Top Layer w10: U2.23 1644.95,661.86 1673.62,633.19 D3.2@1674.65,632.17
RST: C12.2 J6.1 R22.2 U2.25 | length 1368.1
  Top Layer w10: J6.1 1574.65,208.74 1754.65,208.74 1774.65,188.74 1774.65,138.74 1804.65,108.74 1849.65,108.74 1874.65,133.74 1874.65,209.96 1854.65,229.96 1854.65,718.7 1829.61,743.74 1809.65,743.74 1803.04,750.35 C12.2@1794.65,758.74 ; U2.25@1734.65,944.36 1744.02,944.36 1744.65,943.74 1744.65,878.74 1759.65,863.74 1794.65,863.74 R22.2 C12.2@1794.65,758.74 ; C12.2@1794.65,748.74 C12.2@1794.65,758.74
RST_CTRL_51: R19.1 R20.1 U2.41 | length 455
  Top Layer w10: U2.41 1585.89,1267.86 1623.03,1305 1754.61,1305 1764.65,1315.04 R20.1@1764.65,1455.74 ; R19.1 R20.1@1764.65,1455.74 ; R20.1 R20.1@1764.65,1455.74
RST_CTRL_ARM: R23.1 R24.1 U2.40 | length 474.6
  Top Layer w10: U2.40 1605.58,1255.67 1629.91,1280 1764.61,1280 1789.65,1305.04 1789.65,1390.04 R23.1@1847.11,1447.5 ; R23.1 R24.1
TOOL_OPTION0: R2.1 U2.5 | length 135.2
  Top Layer w10: R2.1 1271.56,1082.66 U2.5
TOOL_OPTION1: R3.1 U2.6 | length 156.1
  Top Layer w10: R3.1 1264.65,998.74 1328.88,1062.97 U2.6
USBOK: D2.2 U2.21 | length 430.2
  Top Layer w10: D2.2@1374.65,632.17 1375.67,633.19 1427.48,685 1568.07,685 1605.58,722.51 U2.21
VCC_USB: C2.1 D14.1 J1.1 Q1.2 R1.1 | length 843.2
  Top Layer w30: 2024.61,1076.22 2044.61,1076.22 2112.09,1076.22 2147.09,1111.22 2147.09,1212.52 2109.61,1250 2109.61,1367 C2.1@2114.53,1371.92 ; Q1.2 2116.65,1458.74 ; 2114.53,1445.62 2114.53,1380 C2.1@2114.53,1371.92 ; C2.1 C2.1@2114.53,1371.92 ; R1.1@2129.65,1455.74 R1.1 2171.61,1455.74 2189.61,1473.74 D14.1@2189.61,1697.13
VCP_OPTION: J3.1 U2.8 | length 722
  Top Layer w10: v4(1124.61,888.74) 1249.65,888.74 1299.65,938.74 1299.65,993.74 1329.51,1023.6 U2.8
  Bottom Layer w12: J3.1 1024.65,788.78 v4(1124.61,888.74)
VDD: C12.1 J2.2 J6.4 R4.1 R6.1 R9.1 R10.1 R11.1 R12.1 R13.1 R14.2 SW1.2 | length 3588.5
  Top Layer w11: 1782.65,380.74 1804.65,358.74 ; 1789.65,388.74 1807.65,406.74
  Top Layer w20: v5@1152.72,1213.74 R13.1@1186.65,1213.74 ; v5@1157.72,1223.74 R13.1@1191.65,1223.74 ; R12.1@1193.65,1148.74 R13.1@1193.65,1218.3
  Top Layer w30: v10(1199.65,578.74) 1199.65,480.7 1299.61,380.74 1374.65,380.74 1524.65,380.74 1674.65,380.74 1782.65,380.74 1807.65,380.74 ; R14.2@1389.61,1526.74 1384.61,1526.74 1336.61,1526.74 v5(1334.61,1528.74) 1329.61,1533.74 1329.61,1738.74 1578.36,1987.49 1588.43,1987.49 1593.42,1982.51 1599.65,1976.28 1605.88,1982.51 1694.11,2070.74 R4.1 1753.61,2070.74 1806.61,2123.74 J2.2 ; R14.2@1394.61,1526.74 R10.1@1454.61,1526.74 ; C12.1@1814.65,643.53 1814.65,168.74 J6.4 J6.4@1824.65,168.74
  Bottom Layer w30: v5(1149.65,1218.74) 1199.65,1218.74 ; v10(1199.65,578.74) 1199.65,1218.74 ; v5(1334.61,1528.74) 1334.61,1318.7 1234.65,1218.74 1199.65,1218.74
VDD3: C5.1 J2.3 U1.1 | length 231.2
  Top Layer w40: J2.3 1950.91,2270 C5.1@2034.61,2270 ; U1.1@2034.61,2193.74 C5.1@2034.61,2270 ; C5.1 C5.1@2034.61,2270
VDD5: C4.1 D1.2 J2.1 U1.3 | length 318.5
  Top Layer w40: J2.1@1903.17,2022.26 1955.43,1970 C4.1@2029.61,1970 ; D1.2@2029.61,1900.35 C4.1@2029.61,1970 ; U1.3 C4.1@2029.61,1970 ; C4.1 C4.1@2029.61,1970
VDUT: D5.2 D7.1 J4.3 J7.3 J11.1 J11.2 J11.3 J11.4 J17.3 J18.1 J19.3 Q2.2 R7.1 R58.2 | length 4255.3
  Top Layer w15: R7.1 1189.65,1389.74 1189.65,1614.24 1204.65,1629.24 1214.65,1639.24 ; v5@1222.4,1611.49 v5@1224.65,1613.74
  Top Layer w20: D5.2@1442.76,2173.74 1476.22,2173.74 D5.2@1493.74,2173.74
  Top Layer w30: J19.3 375,1540 575,1740 J18.1 744.65,1740 ; J11.3 849.55,2133.84 849.55,1865 809.55,1825 774.09,1825 744.65,1795.55 744.65,1740 ; J4.3 J7.3 779.65,1558.74 744.65,1593.74 744.65,1740 ; v5(1214.65,1619.24) 1214.65,1639.24 1214.65,1759.65 1473.74,2018.74 D5.2@1473.74,2168.74 ; v6@1399.61,1619.24 1399.61,1689.68 Q2.2@1412.61,1702.68 ; D5.2@1488.74,2168.74 1493.74,2173.74 1516.5,2196.5 1662.4,2196.5 J17.3
  Top Layer w40: D7.1@335.43,2258.74 409.65,2258.74 ; 379.65,2258.74 409.65,2258.74 ; 409.65,2258.74 487.8,2258.74 524.65,2258.74 J11.2 ; J11.2 J11.1 J11.3 J11.4 J11.2
  Bottom Layer w30: J4.3@1042.68,1559.24 1102.68,1619.24 v5(1214.65,1619.24) v6@1399.61,1619.24
  other v6: 1399.61,1618.74
pads on no net: J6.6 J7.1 U2.1 U2.2 U2.3 U2.4 U2.7 U2.24 U2.28 U2.29 U2.30 U2.32 U2.37 U2.38 U2.39 U2.46 U4.1 U4.2 U4.8 U4.9 U4.10

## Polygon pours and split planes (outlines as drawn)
GND_POWER on Bottom Layer "Top Layer-No Net" (hatched 90Degree grid 10 track 10, remove dead copper, pour order 1001): 24.09,28.74 2214.65,28.74 2214.65,2608.74 24.09,2608.74
GND_POWER on Top Layer "Top Layer-No Net" (hatched 90Degree grid 10 track 10, remove dead copper, pour order 1001): 24.09,28.74 2214.65,28.74 2214.65,2608.74 24.09,2608.74

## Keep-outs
Keep-Out Layer:
  circle w7.88: c140,2497.8 r122.58
  circle w7.88: c762.99,2497.8 r122.58
  circle w7.88: c130,130 r122.58
  circle w7.88: c774.65,130 r122.58
  lines w15: 2244.09,0 2244.09,2637.8

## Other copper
Top Layer:
  pour cut-out: 864.65,2637.8 984.65,2637.8 984.65,-1.26 864.65,-1.26
Bottom Layer:
  pour cut-out: 864.65,2637.8 984.65,2637.8 984.65,-1.26 864.65,-1.26

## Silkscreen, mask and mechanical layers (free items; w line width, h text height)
Top Overlay:
  circle w5: c762.99,2497.8 r120
  circle w5: c140,2497.8 r120
  circle w5: c130,130 r120
  circle w5: c774.65,130 r120
  rectangle: 264.09,110 322.09,152
  rectangle: 264.09,60 322.09,102
  rectangle: 264.09,10 322.09,52
  text "GND" at 269.65,2565 h50
  text "When J16 Open," at 989.65,2333.74 h45
  text "SCL" at 2044.65,2318.74 h35 r90
  text "CLK" at 2144.65,2318.74 h35 r90
  text "Power" at 239.55,2315 h50
  text "RST" at 1644.65,2308.74 h37 r90
  text "GND" at 1744.65,2303.74 h37 r90
  text "SDA" at 1844.65,2303.74 h37 r90
  text "VCC" at 1944.65,2303.74 h37 r90
  text "SW1 must be off." at 989.65,2258.74 h45
  text "VDD3" at 1714.61,2200.64 h37
  text "VDUT" at 659.65,2120 h50 r90
  text "VDD" at 1744.65,2103.74 h37
  text "VDD5" at 1714.61,1990.64 h37
  text "Power On" at 1524.65,1843.74 h45
  text "Power Off" at 1094.65,1838.74 h45
  text "SCL" at 664.65,1623.74 h40
  text "VDUT" at 629.55,1533.74 h40
  text "U4 current" at 479.09,1515 h45 r90
  text "measurement" at 529.09,1510 h40 r90
  text "SDA" at 659.65,1438.74 h40
  text "RESET" at 69.55,1416 h50
  text "GND" at 659.65,1338.74 h40
  text "P47" at 44.65,1238.74 h45
  text "RST" at 664.65,1238.74 h40
  text "P46" at 44.65,1138.74 h45
  text "↓" at 1144.65,1058.74 h100 r90
  text "P45" at 44.65,1038.74 h45
  text "↓" at 754.65,1038.74 h110 r90
  text "P31_TX" at 440,1025 h50
  text "↓" at 704.65,983.74 h110 r270
  text "↓" at 1094.65,958.74 h100 r270
  text "P30_RX" at 440,940 h50
  text "P44" at 44.65,938.74 h45
  text "P33" at 44.65,838.74 h45
  text "P32" at 44.65,738.74 h45
  text "P31" at 44.65,638.74 h45
  text "P30" at 44.65,538.74 h45
  text "P10" at 44.65,438.74 h45
  text "J3 Open : Disable VCP." at 977.65,298.74 h45
  text "2022.03" at 684.09,270 h30
  text "J3 Short : Enable VCP." at 972.65,223.74 h45
  text "TH221A_EV_V11" at 264.09,220 h35
  text "SOP16" at 274.09,165 h35
  text "MG82F6B08" at 339.09,115 h35
  text "MG82F6B001" at 339.09,65 h35
  text "MG82F6B104" at 339.09,15 h35
Mechanical 1:
  circle w7.88: c924.65,1613.74 r27
  circle w7.88: c924.65,1503.74 r27
  circle w7.88: c924.65,1416.74 r25
  circle w7.88: c924.65,1298.74 r25
  circle w7.88: c924.65,1008.74 r33
  lines w7.88: 902.99,1078.74 902.99,1232.74 946.3,1232.74 946.3,1078.74 902.99,1078.74
  lines w8.88: 0,0 902.99,0 902.99,938.74 946.3,938.74 946.3,0 2244.09,0 2244.09,2637.8 946.3,2637.8 946.3,1678.74 902.99,1678.74 902.99,2637.8 0,2637.8 0,0
Mechanical 2:
  lines w6: 924.65,1031.74 924.65,1008.74 947.65,1008.74 ; 924.65,1321.74 924.65,1298.74 947.65,1298.74 ; 924.65,1441.74 924.65,1418.74 947.65,1418.74 ; 924.65,1526.74 924.65,1503.74 947.65,1503.74 ; 924.65,1636.74 924.65,1613.74 947.65,1613.74
Drill Drawing:
  text ".Legend" at 2324.61,15 h40

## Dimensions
0,0 to 2244.09,0 on Top Overlay
0,0 to 0,2637.8 on Top Overlay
